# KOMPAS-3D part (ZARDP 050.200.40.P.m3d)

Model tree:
1. Булева операция:1
2. Булева операция:2
3. Булева операция:3
4. Булева операция:4
5. Булева операция:5
6. Булева операция:6
7. Булева операция:7
8. Булева операция:8
9. Булева операция:9
10. Булева операция:10
11. Булева операция:11
12. Булева операция:12
13. Булева операция:13
14. Булева операция:14
15. Булева операция:15
16. Булева операция:16
17. Булева операция:17
18. Булева операция:18
19. Булева операция:19
20. Булева операция:20
21. Булева операция:38
22. Булева операция:39
23. Булева операция:40
24. Булева операция:41
25. Булева операция:42
26. Булева операция:43
27. Булева операция:44
28. Булева операция:45
29. Булева операция:46
30. Булева операция:47
31. Булева операция:48
32. Булева операция:49
33. Булева операция:50
34. Булева операция:51
35. Булева операция:52
36. Булева операция:53
37. Булева операция:56  (labels: C:\Program Files\ASCON\KOMPAS-3D V13\Sys\graphic.lyt)

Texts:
  ООО ИК Энерпред-Ярдос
